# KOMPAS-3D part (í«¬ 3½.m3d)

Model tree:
1. Эскиз:1
2. Операция выдавливания:1
     Расстояние 1 = 3
3. Эскиз:2
4. Операция выдавливания:2
     Расстояние 1 = 78
5. Эскиз:3
6. Операция выдавливания:3
     Расстояние 1 = 3
7. Эскиз:4
8. Операция выдавливания:4
     Расстояние 1 = 4
9. Эскиз:5
10. Операция выдавливания:5
     Расстояние 1 = 4
11. Эскиз:6
12. Вырезать элемент выдавливания:1
     Расстояние 2 = 110; Расстояние 1 = 100
13. Эскиз:7
14. Вырезать элемент выдавливания:2
     Расстояние 1 = 100
